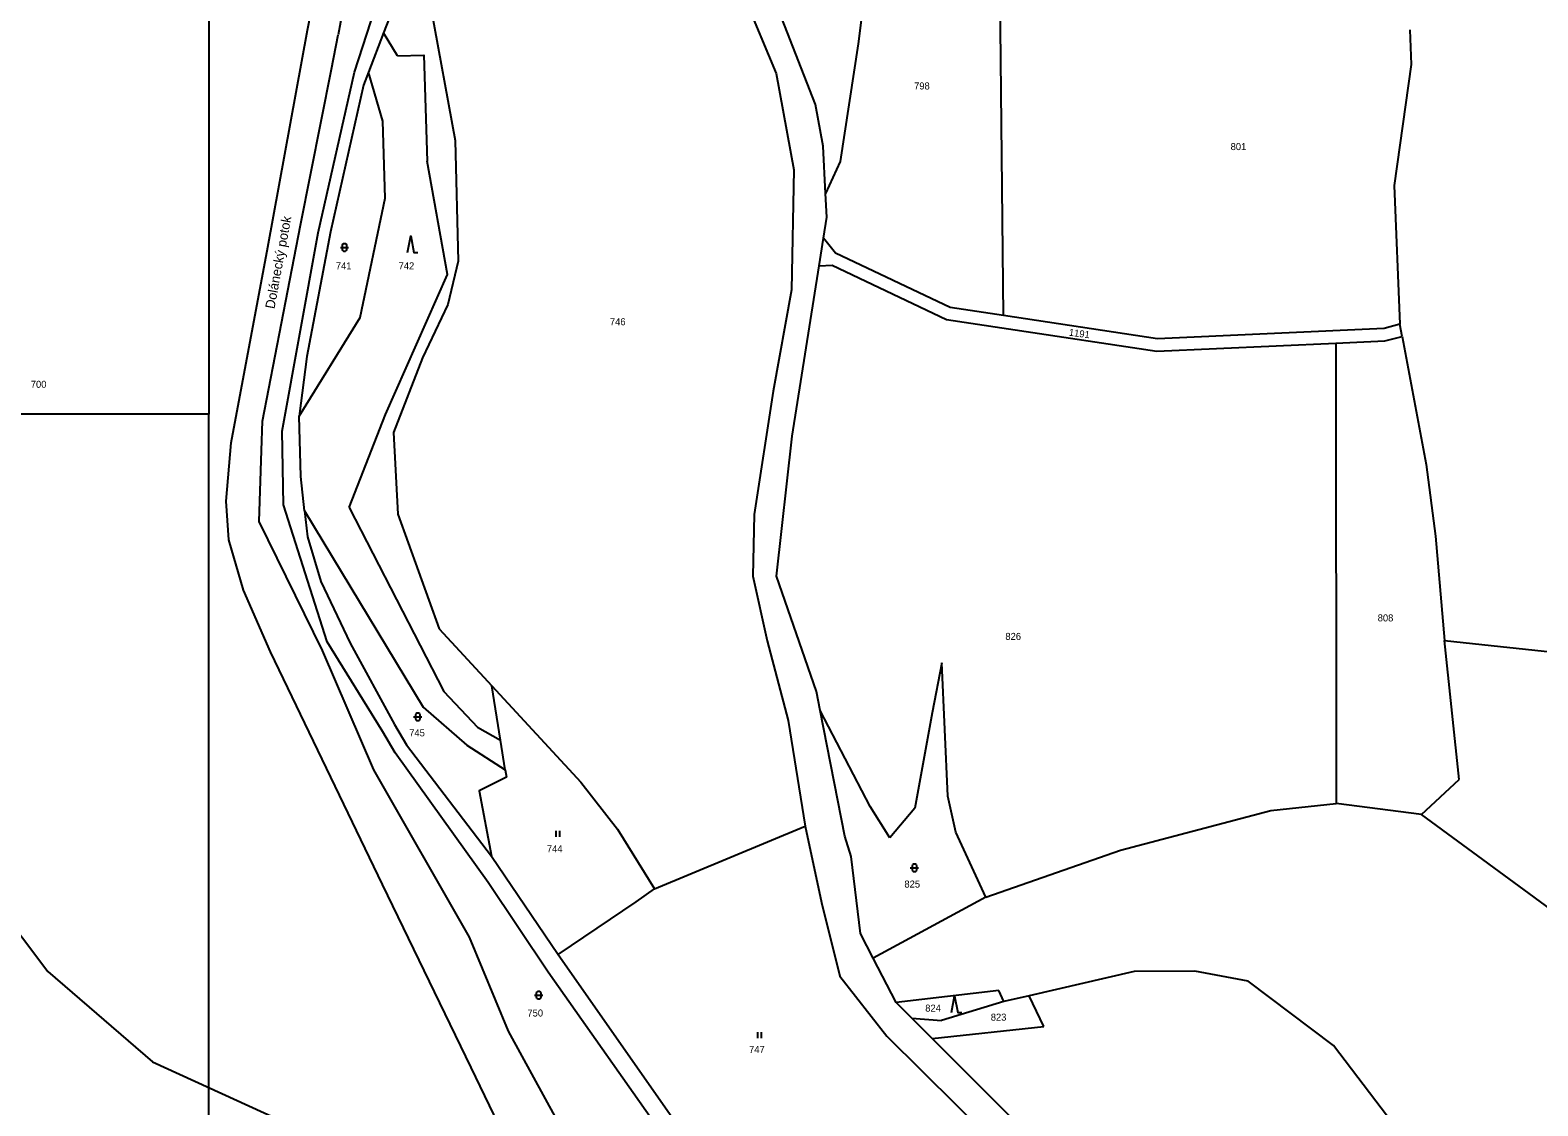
# Model space of a CAD drawing. Extents: x -812394 to -807601, y -1013097 to -1009266.
# Drawn here: x -809418.3 to -809053.2, y -1011167.6 to -1010907 of the extents above; entities that cross this region are included whole.
import ezdxf

# ---------------------------------------------------------------- set-up
doc = ezdxf.new("R2010")
doc.units = 0
for name, color, linetype in [('Default', 7, 'Continuous'), ('KLADY_ZMVM', 7, 'Continuous'), ('KN_HRANICE', 7, 'Continuous'), ('KN_KULTURY', 7, 'Continuous'), ('KN_PARCELY', 7, 'Continuous')]:
    doc.layers.add(name, color=color, linetype=linetype)

# ---------------------------------------------------------------- blocks, each defined once
blk = doc.blocks.new('306')
at = {"layer": 'Default'}
for p, q in [((-0.5, 1.5), (-0.5, 0)), ((0.5, 0), (0.5, 1.5))]:
    blk.add_line(p, q, dxfattribs=at)
blk = doc.blocks.new('308')
at = {"layer": 'Default'}
blk.add_lwpolyline([(-0.75, 0), (0, 4), (0.75, 0), (1.75, 0)], dxfattribs=at)
blk = doc.blocks.new('316')
at = {"layer": 'Default'}
for points in [[(-1, 1), (0.27, 1), (1, 1)], [(-0.5, 1.5), (-0.4, 1.79), (-0.15, 1.97), (0.16, 1.97), (0.41, 1.79), (0.51, 1.5), (0.51, 0.5), (0.41, 0.21), (0.16, 0.03), (-0.15, 0.03), (-0.4, 0.21), (-0.5, 0.5), (-0.5, 1.5)]]:
    blk.add_lwpolyline(points, dxfattribs=at)

msp = doc.modelspace()

# ---------------------------------------------------------------- linework, layer by layer
at = {"layer": 'KLADY_ZMVM'}
for points in [[(-810000, -1011000), (-810000, -1010500), (-809375, -1010500), (-809375, -1011000), (-809466.04, -1011000)], [(-809625.71, -1011000), (-810000, -1011000), (-810000, -1011500), (-809375, -1011500), (-809375, -1011000)]]:
    msp.add_lwpolyline(points, dxfattribs=at)
at = {"layer": 'KN_HRANICE'}
for p, q in [((-809264.15, -1010854.13), (-809237.69, -1010917.44)), ((-809351.15, -1010907.01), (-809342.76, -1010863.71)), ((-809211.78, -1010863.69), (-809217.85, -1010910.29)), ((-809228.17, -1010924.96), (-809242.93, -1010887.17)), ((-809328.19, -1010895.88), (-809332.71, -1010907.64)), ((-809182.59, -1010976.12), (-809183.47, -1010897.59)), ((-809342.56, -1010901.99), (-809343.75, -1010908.11)), ((-809339.74, -1010917.13), (-809334.79, -1010901.69)), ((-809321.27, -1010901.54), (-809315.42, -1010933.7)), ((-809360.75, -1010959.55), (-809351.15, -1010907.01)), ((-809332.71, -1010907.64), (-809336.38, -1010917.18)), ((-809329.36, -1010913.21), (-809332.71, -1010907.64)), ((-809084.22, -1010906.93), (-809083.93, -1010915.3)), ((-809217.85, -1010910.29), (-809222.2, -1010938.83)), ((-809348.56, -1010956.1), (-809339.74, -1010917.13)), ((-809083.93, -1010915.3), (-809088.03, -1010944.58)), ((-809337.58, -1010920.29), (-809345.55, -1010955.82)), ((-809336.38, -1010917.18), (-809337.58, -1010920.29)), ((-809237.69, -1010917.44), (-809233.39, -1010940.77)), ((-809226.26, -1010935.05), (-809228.17, -1010924.96)), ((-809315.42, -1010933.7), (-809314.64, -1010962.96)), ((-809225.71, -1010946.53), (-809226.26, -1010935.05)), ((-809222.2, -1010938.83), (-809225.71, -1010946.53)), ((-809233.39, -1010940.77), (-809233.99, -1010969.84)), ((-809088.03, -1010944.58), (-809086.63, -1010978.22)), ((-809225.43, -1010952.31), (-809225.71, -1010946.53)), ((-809226.21, -1010957.33), (-809225.43, -1010952.31)), ((-809357.31, -1011004.14), (-809348.56, -1010956.1)), ((-809345.55, -1010955.82), (-809351.29, -1010986.02)), ((-809369.66, -1011006.98), (-809360.75, -1010959.55)), ((-809227.25, -1010964.08), (-809226.21, -1010957.33)), ((-809223.26, -1010961.02), (-809226.21, -1010957.33)), ((-809314.64, -1010962.96), (-809317.18, -1010973.46)), ((-809233.82, -1011005.3), (-809227.25, -1010964.08)), ((-809227.25, -1010964.08), (-809224.09, -1010963.94)), ((-809224.09, -1010963.94), (-809196.42, -1010977.07)), ((-809195.54, -1010974.17), (-809223.26, -1010961.02)), ((-809233.99, -1010969.84), (-809238.41, -1010994.42)), ((-809317.18, -1010973.46), (-809323.27, -1010986.38)), ((-809182.59, -1010976.12), (-809195.54, -1010974.17)), ((-809196.42, -1010977.07), (-809145.53, -1010984.73)), ((-809145.37, -1010981.72), (-809182.59, -1010976.12)), ((-809086.63, -1010978.22), (-809090.45, -1010979.23)), ((-809086.08, -1010981.18), (-809086.63, -1010978.22)), ((-809145.53, -1010984.73), (-809102.18, -1010982.77)), ((-809090.45, -1010979.23), (-809145.37, -1010981.72)), ((-809102.18, -1010982.77), (-809090.32, -1010982.23)), ((-809102.18, -1010982.77), (-809102.05, -1011094.31)), ((-809090.32, -1010982.23), (-809086.08, -1010981.18)), ((-809086.08, -1010981.18), (-809080.31, -1011012.17)), ((-809351.29, -1010986.02), (-809353.14, -1011000.49)), ((-809323.27, -1010986.38), (-809330.28, -1011004.43)), ((-809238.41, -1010994.42), (-809243.03, -1011024.27)), ((-809356.99, -1011021.98), (-809357.31, -1011004.14)), ((-809330.28, -1011004.43), (-809329.24, -1011024.22)), ((-809370.8, -1011021.05), (-809369.66, -1011006.98)), ((-809237.57, -1011039.2), (-809233.82, -1011005.3)), ((-809080.31, -1011012.17), (-809078.02, -1011029.54)), ((-809346.38, -1011055.16), (-809356.99, -1011021.98)), ((-809351.85, -1011023.44), (-809351.16, -1011029.72)), ((-809329.24, -1011024.22), (-809319.27, -1011052)), ((-809243.03, -1011024.27), (-809243.29, -1011039.21)), ((-809351.16, -1011029.72), (-809347.94, -1011040.55)), ((-809078.02, -1011029.54), (-809075.88, -1011054.83)), ((-809347.94, -1011040.55), (-809340.8, -1011055.43)), ((-809243.29, -1011039.21), (-809239.88, -1011054.88)), ((-809227.91, -1011067.2), (-809237.57, -1011039.2)), ((-809319.27, -1011052), (-809306.54, -1011065.84)), ((-809332.9, -1011076.93), (-809346.38, -1011055.16)), ((-809340.8, -1011055.43), (-809330.11, -1011075.2)), ((-809239.88, -1011054.88), (-809234.8, -1011074.21)), ((-809072.31, -1011088.53), (-809075.88, -1011054.83)), ((-809075.88, -1011054.83), (-808951.36, -1011068.01)), ((-809197.56, -1011060.27), (-809199.87, -1011072.38)), ((-809196.14, -1011092.51), (-809197.56, -1011060.27)), ((-809306.54, -1011065.84), (-809284.98, -1011089.13)), ((-809304.41, -1011078.99), (-809306.54, -1011065.84)), ((-809227.01, -1011071.76), (-809227.91, -1011067.2)), ((-809214.9, -1011095.05), (-809227.01, -1011071.76)), ((-809221.02, -1011102.26), (-809227.01, -1011071.76)), ((-809199.87, -1011072.38), (-809204.08, -1011095.41)), ((-809329.89, -1011082), (-809332.9, -1011076.93)), ((-809330.11, -1011075.2), (-809327.19, -1011080.12)), ((-809234.8, -1011074.21), (-809230.64, -1011099.78)), ((-809327.19, -1011080.12), (-809306.61, -1011107.09)), ((-809303.25, -1011086.19), (-809304.41, -1011078.99)), ((-809307.36, -1011113.45), (-809329.89, -1011082)), ((-809303.25, -1011086.19), (-809302.97, -1011087.89)), ((-809081.38, -1011096.96), (-809072.31, -1011088.53)), ((-809284.98, -1011089.13), (-809276.12, -1011100.51)), ((-809210.17, -1011102.63), (-809214.9, -1011095.05)), ((-809204.08, -1011095.41), (-809210.17, -1011102.63)), ((-809194.17, -1011101.23), (-809196.14, -1011092.51)), ((-809081.38, -1011096.96), (-809102.05, -1011094.31)), ((-809048.99, -1011120.76), (-809081.38, -1011096.96)), ((-809276.12, -1011100.51), (-809267.11, -1011114.96)), ((-809267.11, -1011114.96), (-809230.64, -1011099.78)), ((-809230.64, -1011099.78), (-809226.7, -1011118.26)), ((-809219.52, -1011107.12), (-809221.02, -1011102.26)), ((-809186.94, -1011117), (-809194.17, -1011101.23)), ((-809437.7, -1011103.69), (-809413.98, -1011135.02)), ((-809306.61, -1011107.09), (-809290.45, -1011130.86)), ((-809217.26, -1011125.81), (-809219.52, -1011107.12)), ((-809292.88, -1011135.16), (-809307.36, -1011113.45)), ((-809271.53, -1011118.12), (-809267.11, -1011114.96)), ((-809186.94, -1011117), (-809214.18, -1011131.75)), ((-809290.45, -1011130.86), (-809271.53, -1011118.12)), ((-809226.7, -1011118.26), (-809222.24, -1011136.1)), ((-809214.18, -1011131.75), (-809217.26, -1011125.81)), ((-809290.45, -1011130.86), (-809244.33, -1011196.74)), ((-809208.59, -1011142.51), (-809214.18, -1011131.75)), ((-809413.98, -1011135.02), (-809388.65, -1011156.86)), ((-809249.48, -1011196.8), (-809292.88, -1011135.16)), ((-809222.24, -1011136.1), (-809210.85, -1011150.65)), ((-809151.01, -1011135.04), (-809176.38, -1011140.9)), ((-809136.28, -1011134.9), (-809151.01, -1011135.04)), ((-809123.42, -1011137.33), (-809136.28, -1011134.9)), ((-809183.77, -1011139.63), (-809208.59, -1011142.51)), ((-809182.51, -1011142.31), (-809183.77, -1011139.63)), ((-809102.71, -1011152.94), (-809123.42, -1011137.33)), ((-809204.83, -1011146.28), (-809208.59, -1011142.51)), ((-809182.51, -1011142.31), (-809197.6, -1011146.91)), ((-809176.38, -1011140.9), (-809182.51, -1011142.31)), ((-809172.88, -1011148.32), (-809176.38, -1011140.9)), ((-809199.91, -1011151.21), (-809204.83, -1011146.28)), ((-809204.83, -1011146.28), (-809197.6, -1011146.91)), ((-809210.85, -1011150.65), (-809177.04, -1011184.11)), ((-809199.91, -1011151.21), (-809172.88, -1011148.32)), ((-809180.8, -1011170.37), (-809199.91, -1011151.21)), ((-809083.49, -1011178.16), (-809102.71, -1011152.94)), ((-809388.65, -1011156.86), (-809355.08, -1011172.25))]:
    msp.add_line(p, q, dxfattribs=at)
for points in [[(-809362.27, -1011008.78), (-809362.03, -1011001.71), (-809352.87, -1010954.23), (-809345.36, -1010916.43), (-809343.75, -1010908.11)], [(-809329.36, -1010913.21), (-809322.98, -1010913.02), (-809322.16, -1010938.75)], [(-809353.14, -1011000.49), (-809338.36, -1010976.54), (-809332.32, -1010947.69), (-809332.87, -1010928.98), (-809336.38, -1010917.18)], [(-809341.02, -1011022.61), (-809332.28, -1011000.05), (-809317.23, -1010966.13), (-809322.16, -1010938.75)], [(-809351.85, -1011023.44), (-809352.77, -1011015.12), (-809353.14, -1011000.49)], [(-809311.9, -1011126.69), (-809335.1, -1011086.13), (-809347.52, -1011057.28), (-809362.87, -1011025.99), (-809362.27, -1011008.78)], [(-809294.96, -1011192.54), (-809311.49, -1011158.23), (-809332.98, -1011113.92), (-809360.07, -1011057.57), (-809366.67, -1011042.66), (-809370.18, -1011030.46), (-809370.8, -1011021.05)], [(-809341.02, -1011022.61), (-809318.1, -1011067.16), (-809309.99, -1011075.82), (-809304.41, -1011078.99)], [(-809351.85, -1011023.44), (-809323.11, -1011070.98), (-809312.59, -1011080.19), (-809303.25, -1011086.19)], [(-809302.97, -1011087.89), (-809309.58, -1011091.26), (-809306.61, -1011107.09)], [(-809186.94, -1011117), (-809154.28, -1011105.63), (-809117.9, -1011095.99), (-809102.05, -1011094.31)], [(-809272.89, -1011193.49), (-809282.21, -1011186.49), (-809302.51, -1011149.43), (-809311.9, -1011126.69)]]:
    msp.add_lwpolyline(points, dxfattribs=at)

# ---------------------------------------------------------------- block references
at = {"layer": 'KN_KULTURY'}
for name, p in [('308', (-809326.16, -1010960.82)), ('316', (-809342.18, -1010960.59)), ('316', (-809324.45, -1011074.33)), ('306', (-809290.53, -1011102.4)), ('316', (-809204.19, -1011110.87)), ('316', (-809295.18, -1011141.73)), ('308', (-809194.47, -1011144.96)), ('306', (-809241.72, -1011151.16))]:
    msp.add_blockref(name, p, dxfattribs=at)

# ---------------------------------------------------------------- texts
at = {"layer": 'KN_PARCELY'}
for s, p in [('798', (-809204.27, -1010921.34)), ('801', (-809127.63, -1010936.03)), ('741', (-809344.29, -1010964.93)), ('742', (-809329.09, -1010964.93)), ('746', (-809277.92, -1010978.45)), ('700', (-809418.14, -1010993.61)), ('808', (-809092.02, -1011050.2)), ('826', (-809182.17, -1011054.68)), ('745', (-809326.52, -1011078.04)), ('744', (-809293.18, -1011106.11)), ('825', (-809206.62, -1011114.67)), ('824', (-809201.57, -1011144.72)), ('750', (-809297.9, -1011145.91)), ('823', (-809185.71, -1011146.91)), ('747', (-809244.23, -1011154.74))]:
    msp.add_text(s, height=1.7, dxfattribs=at).set_placement(p)
for s, height, rotation, p in [('Dolánecký potok', 2.3, 79.527, (-809359.15, -1010974.61)), ('1191', 1.7, 352.484, (-809166.87, -1010980.97))]:
    msp.add_text(s, height=height, rotation=rotation, dxfattribs=at).set_placement(p)

doc.saveas('drawing.dxf')
